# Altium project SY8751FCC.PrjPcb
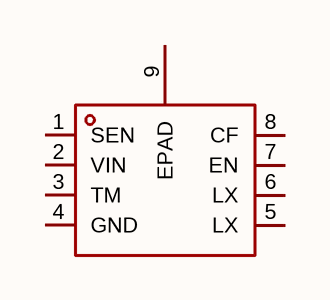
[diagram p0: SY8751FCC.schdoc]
1 sheet, 1 parts. Net scope: global (net labels, ports and power ports of the same name join across sheets).

## Sheet SY8751FCC.schdoc
size 127 x 101 mm

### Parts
U?  sy8751fcc  [SO-8_L4.9-W3.9-P1.27-LS6.0-BL-EP]  (value not drawn)

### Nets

Not connected (* = marked no-connect by the designer): U? 1(SEN) 2(VIN) 3(TM) 4(GND) 5(LX) 6(LX) 7(EN) 8(CF) 9(EPAD)

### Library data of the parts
U? = sy8751fcc: 类型:DC-DC;工作电压(DC):5V~80V;开关频率:500kHz;通道数:1;输出电压:-;输出电流:1.2A;调光:PWM；模拟;拓扑结构:降压;; Manufacturer: Silergy(矽力杰); AddInBom: yes; ModelId: 756fba4e187a48c69a2c935cd5c4465b; ModelName: SO-8_L4.9-W3.9-H1.5-LS5.9-P1.27; ModelTransform: 240.39054,192.913,0,270,0,0,0.004,-0.002,0; Voltage - Input(DC): 5V~80V; Frequency - Switching: 500kHz; Number of Channels: 1; Output Current: 1.2A; Dimming: PWM；模拟; Topology: 降压; Switch Tube (Built-In/External): 内置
